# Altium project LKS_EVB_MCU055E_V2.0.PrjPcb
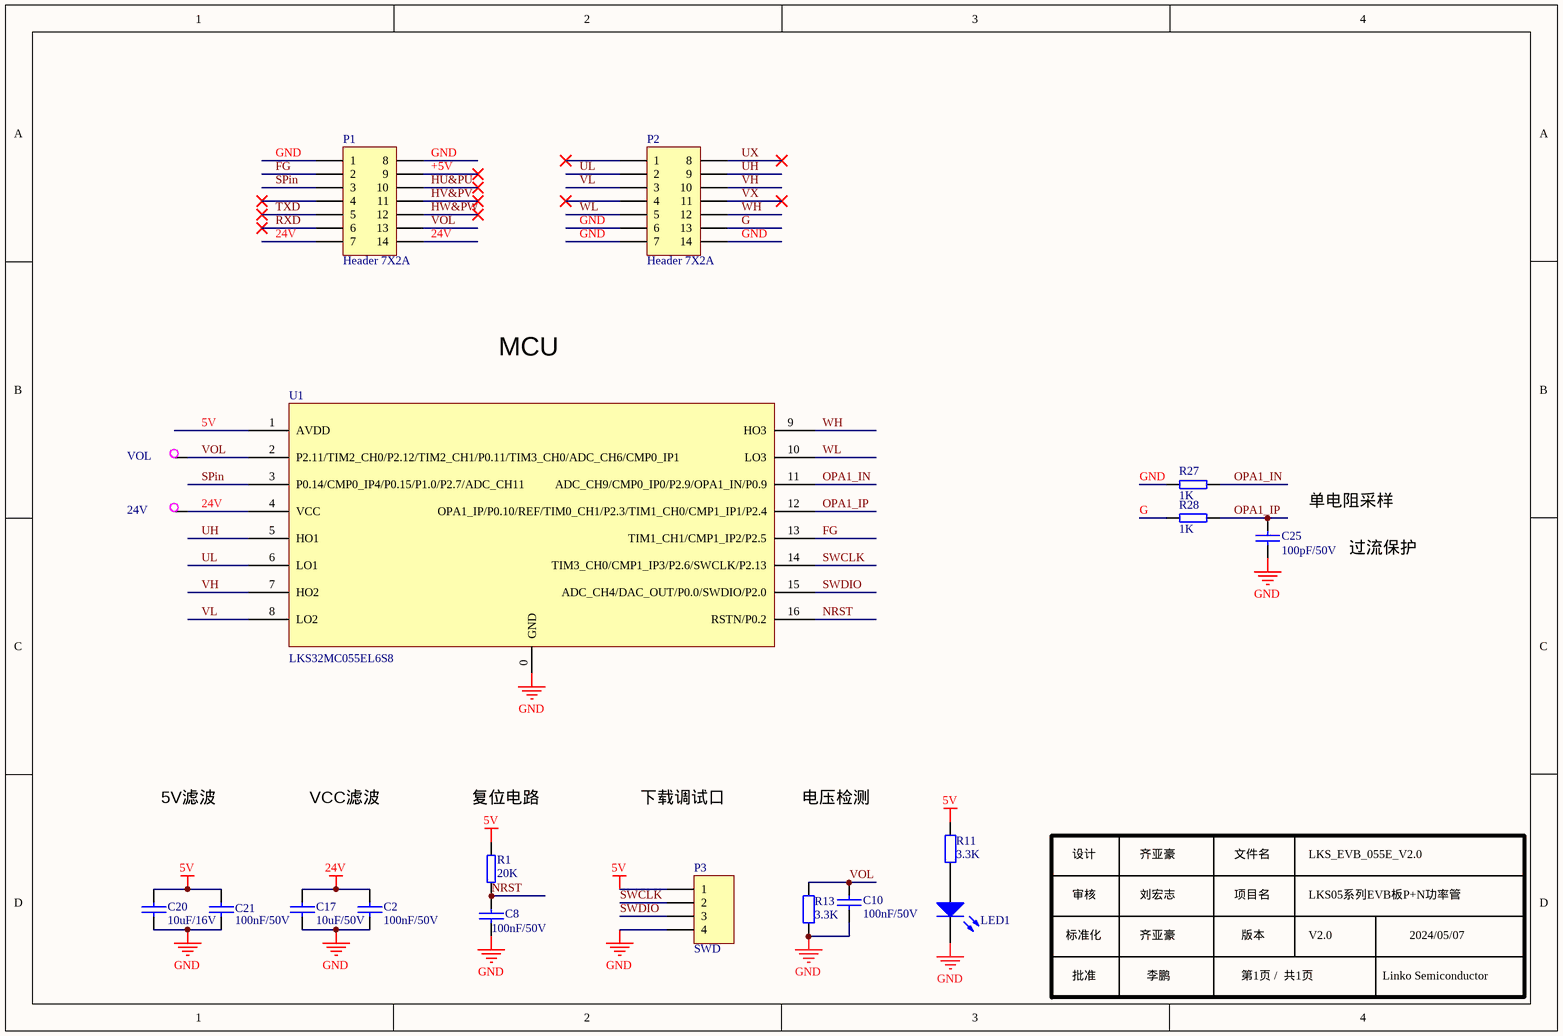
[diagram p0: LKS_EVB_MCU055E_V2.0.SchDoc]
1 sheet, 19 parts. Net scope: global (net labels, ports and power ports of the same name join across sheets).
Board file: LKS_EVB_MCU055E_V2.0.PcbDoc

## Sheet LKS_EVB_MCU055E_V2.0.SchDoc: LKS087_DEMO_V2.0_200109
size A4; Revision: V1.0; SheetNumber: 1; SheetTotal: 1

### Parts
24V  TestP  [TP-80]  (value not drawn)
C2  100nF/50V  [0603C]
C8  100nF/50V  [0603C]
C10  100nF/50V  [0603C]
C17  10uF/50V  [0805C]
C20  10uF/16V  [0603C]
C21  100nF/50V  [0603C]
C25  100pF/50V  [0603C]
LED1  (no value)  [LED 0603R]
P1  Header 7X2A  [HDR2X7_CEN]
P2  Header 7X2A  [HDR2X7_CEN]
P3  SWD  [HDR 1X4]
R1  20K  [0603R]
R11  3.3K  [0603R]
R13  3.3K  [0603R]
R27  1K  [0603R]
R28  1K  [0603R]
U1  LKS32MC055EL6S8  [ESOP16]
VOL  TestP  [TP-80]  (value not drawn)

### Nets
5V: C20.2 C21.1 P3.1 R1.1 R11.2 U1.1(AVDD)
24V: 24V.1 C2.1 C17.2 P1.7 P1.14 U1.4(VCC)
GND: C2.2 C8.2 C10.2 C17.1 C20.1 C21.2 C25.1 LED1.2(K) P1.1 P1.8 P2.6 P2.7 P2.14 P3.4 R13.2 R27.2 U1.0(GND)
+5V: P1.9
FG: P1.2 U1.13(TIM1_CH1/CMP1_IP2/P2.5)
G: P2.13 R28.2
HU&PU: P1.10
HV&PV: P1.11
HW&PW: P1.12
NRST: C8.1 R1.2 U1.16(RSTN/P0.2)
OPA1_IN: R27.1 U1.11(ADC_CH9/CMP0_IP0/P2.9/OPA1_IN/P0.9)
OPA1_IP: C25.2 R28.1 U1.12(OPA1_IP/P0.10/REF/TIM0_CH1/P2.3/TIM1_CH0/CMP1_IP1/P2.4)
RXD: P1.6
SPin: P1.3 U1.3(P0.14/CMP0_IP4/P0.15/P1.0/P2.7/ADC_CH11)
SWCLK: P3.2 U1.14(TIM3_CH0/CMP1_IP3/P2.6/SWCLK/P2.13)
SWDIO: P3.3 U1.15(ADC_CH4/DAC_OUT/P0.0/SWDIO/P2.0)
TXD: P1.5
UH: P2.9 U1.5(HO1)
UL: P2.2 U1.6(LO1)
UX: P2.8
VH: P2.10 U1.7(HO2)
VL: P2.3 U1.8(LO2)
VOL: C10.1 P1.13 R13.1 U1.2(P2.11/TIM2_CH0/P2.12/TIM2_CH1/P0.11/TIM3_CH0/ADC_CH6/CMP0_IP1) VOL.1
VX: P2.11
WH: P2.12 U1.9(HO3)
WL: P2.5 U1.10(LO3)
NetLED1_1: LED1.1(A) R11.1

Not connected (* = marked no-connect by the designer): P1 4*; P2 1* 4*

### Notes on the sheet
- MCU
- 过流保护
- 5V滤波
- VCC滤波
- (near R1) 复位电路
- 设计
- 审核
- 齐亚豪
- 刘宏志
- 文件名
- 项目名
- LKS_EVB_055E_V2.0
- LKS05系列EVB板P+N功率管
- 标准化
- 批准
- 李鹏
- 版本
- 第1页 /  共1页
- V2.0
- Linko Semiconductor
- 2024/05/07
- Labels drawn without touching a wire or pin: GND, 下载调试口, 单电阻采样, 电压检测

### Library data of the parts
C2 C10 C17 C20 C21 = CAP: Capacitor
C8 C25 = C: Capacitor
LED1 = LED2: Typical RED, GREEN, YELLOW, AMBER GaAs LED
P1 P2 = Header 7X2A: Header, 7-Pin, Dual row
P3 = Header 4: Header, 4-Pin
R1 R27 R28 = RES2-1
R11 R13 = Res2: Resistor
U1 = LKS32MC055EL6S8: 芯片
